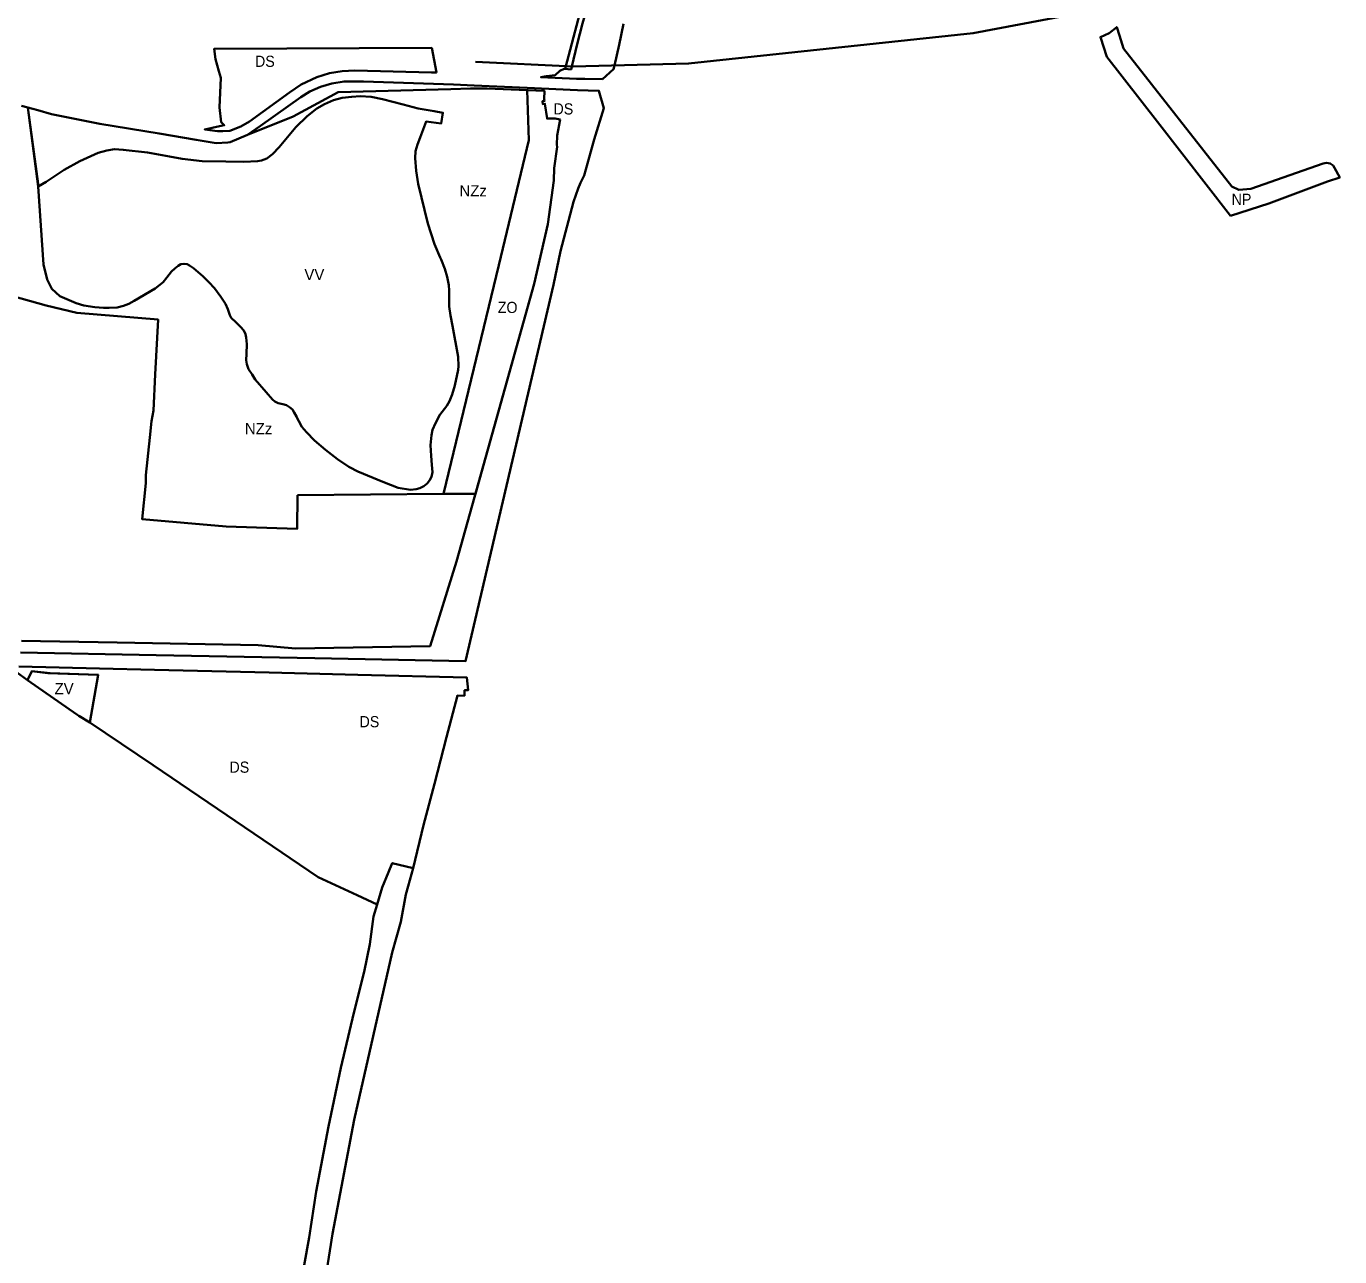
# Model space of a CAD drawing. Extents: x -650276 to -642489, y -1074311 to -1066720.
# Drawn here: x -645637 to -644229, y -1072023 to -1070703 of the extents above; entities that cross this region are included whole.
import ezdxf

# ---------------------------------------------------------------- set-up
doc = ezdxf.new("R2010")
doc.units = 0
doc.header["$LTSCALE"] = 4.8
for name, color, linetype, lineweight in [('15', 7, 'Continuous', 35), ('24', 7, 'Continuous', 35), ('40', 7, 'Continuous', 35), ('42', 7, 'Continuous', 35), ('45', 7, 'Continuous', 35), ('46', 7, 'Continuous', 35), ('48', 7, 'Continuous', 35), ('54', 7, 'Continuous', 35)]:
    doc.layers.add(name, color=color, linetype=linetype, lineweight=lineweight)
doc.layers.add('62', color=7, linetype='Continuous')

msp = doc.modelspace()

# ---------------------------------------------------------------- linework, layer by layer
at = {"layer": '15'}
msp.add_lwpolyline([(-645039.574, -1070675.065), (-645045.493, -1070696.321), (-645059.308, -1070747.712), (-645059.403, -1070749.195), (-645053.21, -1070749.75), (-645052.4, -1070746.427), (-645046.63, -1070722.77), (-645041, -1070700.44), (-645033.53, -1070674.55)], dxfattribs=at)
at = {"layer": '24'}
for points in [[(-645041, -1070700.44), (-645046.63, -1070722.77), (-645052.4, -1070746.427), (-645053.21, -1070749.75), (-645060.46, -1070749.1), (-645065.17, -1070751.39), (-645070.3, -1070755.92), (-645079.38, -1070756.91), (-645085.58, -1070758.04), (-645047.39, -1070759.71), (-645038.44, -1070759.83), (-645019.57, -1070760.07), (-645007.68, -1070749.5), (-645006.739, -1070745.384), (-645001.71, -1070723.39), (-644997.14, -1070700.88)], [(-645643.56, -1071374.75), (-645497.84, -1071377.53), (-645327.76, -1071380.76), (-645166.34, -1071384.07), (-645071.99, -1070980.72), (-645064.39, -1070944.7), (-645050.47, -1070891.48), (-645045.74, -1070877.19), (-645043, -1070871.35), (-645039.25, -1070863.33), (-645028.25, -1070824.83), (-645018.18, -1070791.34), (-645023.25, -1070772.62), (-645046.46, -1070771.98), (-645100.32, -1070769.5), (-645156.988, -1070766.884), (-645179.18, -1070765.86), (-645275.8, -1070762.66), (-645296.51, -1070762.52), (-645309.78, -1070764.88), (-645321.9, -1070768.47), (-645333.12, -1070773.33), (-645342.94, -1070779.31), (-645385.99, -1070810.35), (-645400.05, -1070819.84), (-645351, -1070800), (-645303, -1070774), (-645182, -1070771), (-645161, -1070770), (-645143, -1070770), (-645081.75, -1070772.79), (-645081.85, -1070781.59), (-645081.57, -1070783.53), (-645083.95, -1070783.89), (-645083.49, -1070786.92), (-645081.13, -1070786.56), (-645081.13, -1070786.56), (-645078.85, -1070802.46), (-645070.2, -1070802.33), (-645065.01, -1070803.22), (-645068.07, -1070820.37), (-645068.52, -1070830.52), (-645068.07, -1070832.72), (-645071.18, -1070855.63), (-645071.77, -1070868.73), (-645078.23, -1070915.65), (-645092.67, -1070979.52), (-645176.14, -1071277.26), (-645204.341, -1071368.19), (-645348.55, -1071370.559), (-645388.619, -1071366.991), (-645539.738, -1071364.092), (-645642.431, -1071362.259)], [(-645647.727, -1071396.036), (-645635.795, -1071404.403), (-645631.44, -1071394.9), (-645614.201, -1071396.844), (-645560.11, -1071398.7), (-645569.07, -1071449.88), (-645501.37, -1071495.68), (-645393.34, -1071568.75), (-645324.17, -1071615.53), (-645324.17, -1071615.53), (-645305.78, -1071624.13), (-645282.54, -1071634.997), (-645261.094, -1071645.025), (-645255.662, -1071626.67), (-645248.786, -1071610.383), (-645244.81, -1071600.61), (-645222.48, -1071606.08), (-645222.48, -1071606.08), (-645211.27, -1071560.01), (-645199.61, -1071515.68), (-645186.67, -1071465.55), (-645175.06, -1071420.93), (-645167.58, -1071421.19), (-645167.37, -1071415.2), (-645163.56, -1071415.3), (-645164.76, -1071401.79), (-645281.92, -1071398.82), (-645376.87, -1071396.41), (-645499.65, -1071393.3), (-645558.9, -1071391.8), (-645645.368, -1071389.96)], [(-645339.904, -1072462.677), (-645347.551, -1072443.527), (-645347.677, -1072391.355), (-645346.62, -1072330.914), (-645343.458, -1072278.998), (-645339.908, -1072235.158), (-645335.367, -1072185.207), (-645325.498, -1072102.789), (-645309.01, -1071998.147), (-645285.617, -1071875.733), (-645244.798, -1071696.585), (-645235.793, -1071663.703), (-645230.436, -1071634.261), (-645227.905, -1071625.277), (-645222.48, -1071606.08)], [(-645339.904, -1072462.677), (-645347.551, -1072443.527), (-645347.677, -1072391.355), (-645346.62, -1072330.914), (-645343.458, -1072278.998), (-645339.908, -1072235.158), (-645335.367, -1072185.207), (-645325.498, -1072102.789), (-645309.01, -1071998.147), (-645285.617, -1071875.733), (-645244.798, -1071696.585), (-645235.793, -1071663.703), (-645230.436, -1071634.261), (-645227.905, -1071625.277), (-645222.48, -1071606.08)], [(-645222.48, -1071606.08), (-645244.81, -1071600.61), (-645248.786, -1071610.383), (-645255.662, -1071626.67)], [(-645222.48, -1071606.08), (-645244.81, -1071600.61), (-645248.786, -1071610.383), (-645255.662, -1071626.67)], [(-645255.662, -1071626.67), (-645261.094, -1071645.025), (-645264.841, -1071657.687), (-645269.077, -1071687.396), (-645274.868, -1071717.176), (-645286.175, -1071761.228), (-645300.076, -1071820.179), (-645313.153, -1071883.081), (-645326.343, -1071952.807)], [(-645255.662, -1071626.67), (-645261.094, -1071645.025), (-645264.841, -1071657.687), (-645269.077, -1071687.396), (-645274.868, -1071717.176), (-645286.175, -1071761.228), (-645300.076, -1071820.179), (-645313.153, -1071883.081)], [(-645313.153, -1071883.081), (-645326.343, -1071952.807), (-645334.118, -1072001.954), (-645339.455, -1072031.565), (-645344.819, -1072081.225), (-645351.358, -1072130.815), (-645361.317, -1072232.824), (-645364.435, -1072280.268), (-645366.951, -1072331.609), (-645370.624, -1072401.447), (-645372.228, -1072438.764)], [(-645326.343, -1071952.807), (-645334.118, -1072001.954), (-645339.455, -1072031.565), (-645344.819, -1072081.225), (-645351.358, -1072130.815), (-645361.317, -1072232.824), (-645364.435, -1072280.268), (-645366.951, -1072331.609), (-645370.624, -1072401.447), (-645372.228, -1072438.764)]]:
    msp.add_lwpolyline(points, dxfattribs=at)
msp.add_lwpolyline([(-645202.41, -1070726.571), (-645197.539, -1070753.128), (-645202.96, -1070752.89), (-645285.11, -1070750.69), (-645298.41, -1070751.48), (-645312.2, -1070753.77), (-645325.82, -1070757.94), (-645342.41, -1070765.76), (-645354.98, -1070774.28), (-645398.04, -1070805.44), (-645407.37, -1070810.95), (-645419.18, -1070815.44), (-645426.36, -1070815.78), (-645432.07, -1070816.05), (-645445.81, -1070814.06), (-645429.993, -1070810.647), (-645424.969, -1070809.563), (-645428.39, -1070806.09), (-645430, -1070790.68), (-645428.73, -1070758.67), (-645430.84, -1070751.43), (-645434.53, -1070738.77), (-645435.711, -1070727.497)], close=True, dxfattribs=at)
at = {"layer": '40'}
msp.add_lwpolyline([(-645583.18, -1071441.3), (-645580.947, -1071442.658), (-645569.07, -1071449.88), (-645560.11, -1071398.7), (-645611.58, -1071397.14), (-645631.44, -1071394.9), (-645635.795, -1071404.403)], close=True, dxfattribs=at)
at = {"layer": '42'}
for points in [[(-645155.777, -1071204.626), (-645092.67, -1070979.52), (-645078.23, -1070915.65), (-645071.77, -1070868.73), (-645071.18, -1070855.63), (-645068.07, -1070832.72), (-645068.52, -1070830.52), (-645068.07, -1070820.37), (-645065.01, -1070803.22), (-645070.2, -1070802.33), (-645078.85, -1070802.46), (-645081.13, -1070786.56), (-645081.13, -1070786.56), (-645083.49, -1070786.92), (-645083.95, -1070783.89), (-645081.57, -1070783.53), (-645081.85, -1070781.59), (-645081.75, -1070772.79), (-645100.268, -1070771.946)], [(-645100.268, -1070771.946), (-645098.438, -1070825.558), (-645130.749, -1070959.561)], [(-645130.749, -1070959.561), (-645130.749, -1070959.561), (-645189.902, -1071204.885)], [(-645189.902, -1071204.885), (-645186.64, -1071204.86), (-645155.777, -1071204.626)]]:
    msp.add_lwpolyline(points, dxfattribs=at)
at = {"layer": '45'}
for points in [[(-645192.548, -1070953.47), (-645193.51, -1070951.2), (-645199.714, -1070937.126), (-645206.872, -1070914.991), (-645216.991, -1070872.38), (-645219.351, -1070858.481), (-645220.312, -1070845.02), (-645219.787, -1070837.502), (-645217.778, -1070830.159), (-645215.063, -1070822.589), (-645208.696, -1070805.535), (-645192.298, -1070807.665), (-645190.59, -1070796.152), (-645200.111, -1070794.621), (-645217.086, -1070791.58), (-645233.003, -1070787.399), (-645255.407, -1070781.443), (-645267.315, -1070779.162), (-645279.349, -1070778.402), (-645288.343, -1070778.909), (-645298.731, -1070780.176), (-645307.923, -1070782.557), (-645317.677, -1070786.866), (-645325.785, -1070791.428), (-645336.046, -1070799.793), (-645348.318, -1070811.675), (-645366.02, -1070832.94), (-645373.241, -1070840.417), (-645379.448, -1070845.106), (-645385.148, -1070847.387), (-645389.329, -1070848.148), (-645404.15, -1070848.781), (-645423.364, -1070848.402), (-645448.7, -1070847.895), (-645470.235, -1070845.487), (-645483.61, -1070843.208), (-645507.299, -1070838.899), (-645533.268, -1070835.731), (-645542.642, -1070835.35), (-645550.832, -1070836.602), (-645560.079, -1070839.137), (-645579.841, -1070848.008), (-645596.689, -1070857.387), (-645615.817, -1070870.187), (-645624.321, -1070875.224), (-645618.798, -1070958.861), (-645615, -1070975), (-645610, -1070985), (-645601.41, -1070992.83), (-645583.707, -1071000.16), (-645575.406, -1071002.782), (-645563.698, -1071004.618), (-645554.524, -1071005.405), (-645548.534, -1071005.316), (-645539.622, -1071004.966), (-645533.156, -1071003.131), (-645527.302, -1071001.033), (-645521.535, -1070997.886), (-645499.204, -1070984.54), (-645494.223, -1070980.781), (-645490.641, -1070977.722), (-645486.534, -1070972.652), (-645481.466, -1070966.271), (-645477.971, -1070963.036), (-645474.301, -1070960.414), (-645471.418, -1070958.578), (-645468.185, -1070957.966), (-645464.865, -1070958.491), (-645462.069, -1070959.89), (-645457.875, -1070962.949), (-645452.982, -1070967.057), (-645448.001, -1070971.341), (-645441.361, -1070977.635), (-645435.443, -1070984.082), (-645428.541, -1070993.348), (-645423.648, -1071000.865), (-645421.21, -1071006.61), (-645419.026, -1071013.254), (-645417.453, -1071016.051), (-645412.735, -1071020.771), (-645407.492, -1071025.841), (-645404.172, -1071029.687), (-645402.194, -1071033.492), (-645401.408, -1071037.251), (-645400.796, -1071044.157), (-645401.233, -1071054.647), (-645401.408, -1071061.465), (-645400.796, -1071065.748), (-645398.979, -1071070.938), (-645395.234, -1071076.602), (-645395.222, -1071076.62), (-645391.902, -1071082.302), (-645380.193, -1071095.851), (-645373.291, -1071103.543), (-645370.698, -1071105.6), (-645367.028, -1071107.348), (-645362.223, -1071108.484), (-645358.326, -1071109.586), (-645358.203, -1071109.621), (-645354.883, -1071111.631)], [(-645354.883, -1071111.631), (-645353.555, -1071112.92), (-645352, -1071114.429), (-645349.99, -1071117.401), (-645347.631, -1071121.771), (-645345.097, -1071126.754), (-645341.689, -1071132.873), (-645336.884, -1071138.467), (-645328.059, -1071147.471), (-645316.308, -1071157.576), (-645303.551, -1071167.541), (-645291.581, -1071175.845), (-645290.83, -1071176.217), (-645281.707, -1071180.74), (-645254.845, -1071191.919), (-645238.506, -1071198.212), (-645225.487, -1071200.398), (-645225.487, -1071200.398), (-645219.283, -1071199.786), (-645215.351, -1071198.562), (-645211.07, -1071196.464), (-645207.575, -1071193.492), (-645205.049, -1071190.531), (-645202.777, -1071186.423), (-645201.903, -1071181.615), (-645202.34, -1071173.66), (-645203.301, -1071164.132), (-645203.738, -1071152.537), (-645202.951, -1071141.698), (-645201.648, -1071136.226), (-645198.678, -1071128.971), (-645193.872, -1071120.142), (-645186.284, -1071110.216), (-645183.401, -1071105.408), (-645180.692, -1071098.24), (-645177.809, -1071088.625), (-645174.225, -1071071.8), (-645173.788, -1071067.691), (-645174.225, -1071057.989), (-645180.164, -1071024.56), (-645182.261, -1071013.633), (-645183.746, -1071003.786), (-645183.833, -1070986.74), (-645184.357, -1070981.146), (-645185.843, -1070972.23), (-645188.377, -1070963.313), (-645192.548, -1070953.47)]]:
    msp.add_lwpolyline(points, dxfattribs=at)
at = {"layer": '46'}
for points in [[(-645161, -1070770), (-645182, -1070771), (-645303, -1070774), (-645351, -1070800), (-645400.05, -1070819.84), (-645418.67, -1070827.72), (-645421.09, -1070827.89), (-645433.49, -1070828.76), (-645455.184, -1070825.042), (-645494.82, -1070818.45), (-645558.3, -1070808), (-645610.25, -1070797.55), (-645625, -1070793.5), (-645635.482, -1070790.628), (-645624.513, -1070872.314), (-645624.321, -1070875.224), (-645615.817, -1070870.187), (-645596.689, -1070857.387), (-645579.841, -1070848.008), (-645560.079, -1070839.137), (-645550.832, -1070836.602), (-645542.642, -1070835.35), (-645533.268, -1070835.731), (-645507.299, -1070838.899), (-645483.61, -1070843.208), (-645470.235, -1070845.487), (-645448.7, -1070847.895), (-645423.364, -1070848.402), (-645404.15, -1070848.781), (-645389.329, -1070848.148), (-645385.148, -1070847.387), (-645379.448, -1070845.106), (-645373.241, -1070840.417), (-645366.02, -1070832.94), (-645348.318, -1070811.675), (-645336.046, -1070799.793), (-645325.785, -1070791.428), (-645317.677, -1070786.866), (-645307.923, -1070782.557), (-645298.731, -1070780.176), (-645288.343, -1070778.909), (-645279.349, -1070778.402), (-645267.315, -1070779.162), (-645255.407, -1070781.443), (-645233.003, -1070787.399), (-645217.086, -1070791.58), (-645200.111, -1070794.621), (-645190.59, -1070796.152), (-645192.298, -1070807.665), (-645208.696, -1070805.535), (-645215.063, -1070822.589), (-645217.778, -1070830.159), (-645219.787, -1070837.502), (-645220.312, -1070845.02), (-645219.351, -1070858.481), (-645216.991, -1070872.38), (-645206.872, -1070914.991), (-645199.714, -1070937.126), (-645193.51, -1070951.2), (-645192.548, -1070953.47), (-645188.377, -1070963.313), (-645185.843, -1070972.23), (-645184.357, -1070981.146), (-645183.833, -1070986.74), (-645183.746, -1071003.786), (-645182.261, -1071013.633), (-645180.164, -1071024.56), (-645174.225, -1071057.989), (-645173.788, -1071067.691), (-645173.788, -1071067.691), (-645174.225, -1071071.8), (-645177.809, -1071088.625), (-645180.692, -1071098.24), (-645183.401, -1071105.408), (-645183.401, -1071105.408), (-645186.284, -1071110.216), (-645193.872, -1071120.142), (-645193.872, -1071120.142), (-645198.678, -1071128.971), (-645198.678, -1071128.971), (-645201.648, -1071136.226), (-645202.951, -1071141.698), (-645202.951, -1071141.698), (-645203.738, -1071152.537), (-645203.738, -1071152.537), (-645203.301, -1071164.132), (-645202.34, -1071173.66), (-645201.903, -1071181.615), (-645201.903, -1071181.615), (-645202.777, -1071186.423), (-645202.777, -1071186.423), (-645205.049, -1071190.531), (-645207.575, -1071193.492), (-645207.575, -1071193.492), (-645211.07, -1071196.464), (-645211.07, -1071196.464), (-645215.351, -1071198.562), (-645219.283, -1071199.786), (-645219.283, -1071199.786), (-645225.487, -1071200.398), (-645225.487, -1071200.398)], [(-645346.31, -1071206.07), (-645189.902, -1071204.885), (-645130.749, -1070959.561), (-645098.438, -1070825.558), (-645100.268, -1070771.946), (-645143, -1070770), (-645161, -1070770)], [(-645225.487, -1071200.398), (-645238.506, -1071198.212), (-645254.845, -1071191.919), (-645281.707, -1071180.74), (-645290.83, -1071176.217), (-645291.581, -1071175.845), (-645303.551, -1071167.541), (-645316.308, -1071157.576), (-645328.059, -1071147.471), (-645336.884, -1071138.467), (-645341.689, -1071132.873), (-645345.097, -1071126.754), (-645349.99, -1071117.401), (-645352, -1071114.429), (-645354.883, -1071111.631), (-645358.203, -1071109.621), (-645362.223, -1071108.484), (-645367.028, -1071107.348), (-645370.698, -1071105.6), (-645373.291, -1071103.543), (-645380.193, -1071095.851), (-645391.902, -1071082.302), (-645395.222, -1071076.62), (-645398.979, -1071070.938), (-645400.796, -1071065.748), (-645401.408, -1071061.465), (-645401.233, -1071054.647), (-645400.796, -1071044.157), (-645401.408, -1071037.251), (-645402.194, -1071033.492), (-645404.172, -1071029.687), (-645407.492, -1071025.841), (-645412.735, -1071020.771), (-645417.453, -1071016.051), (-645419.026, -1071013.254), (-645421.21, -1071006.61), (-645423.648, -1071000.865), (-645428.541, -1070993.348), (-645435.443, -1070984.082), (-645441.361, -1070977.635), (-645448.001, -1070971.341), (-645457.875, -1070962.949), (-645462.069, -1070959.89), (-645464.865, -1070958.491), (-645468.185, -1070957.966), (-645471.418, -1070958.578), (-645474.301, -1070960.414), (-645477.971, -1070963.036), (-645481.466, -1070966.271), (-645486.534, -1070972.652), (-645490.641, -1070977.722), (-645494.223, -1070980.781), (-645499.204, -1070984.54), (-645521.535, -1070997.886), (-645527.302, -1071001.033), (-645533.156, -1071003.131), (-645539.622, -1071004.966), (-645548.534, -1071005.316), (-645554.524, -1071005.405), (-645563.698, -1071004.618), (-645575.406, -1071002.782), (-645583.707, -1071000.16), (-645601.41, -1070992.83), (-645610, -1070985), (-645615, -1070975), (-645618.798, -1070958.861), (-645624.321, -1070875.224), (-645635.482, -1070790.628), (-645642.52, -1070788.7)], [(-645676.292, -1070985.89), (-645615.899, -1071002.753), (-645583.18, -1071010.7), (-645495.87, -1071017.81), (-645498.931, -1071076.631)], [(-645498.931, -1071076.631), (-645500.94, -1071115.24), (-645503.08, -1071126.98), (-645504.79, -1071144.18), (-645508.912, -1071184.7)], [(-645508.912, -1071184.7), (-645509.22, -1071193.44), (-645512.84, -1071231.9), (-645423.08, -1071239.85)], [(-645423.08, -1071239.85), (-645346.67, -1071242.07), (-645346.31, -1071206.07)]]:
    msp.add_lwpolyline(points, dxfattribs=at)
at = {"layer": '48'}
msp.add_lwpolyline([(-644346.21, -1070906.61), (-644305.07, -1070893.39), (-644242.29, -1070869.82), (-644229.12, -1070865.52), (-644234.66, -1070855.08), (-644236.3, -1070852.87), (-644239.47, -1070850.71), (-644243.15, -1070849.89), (-644246.93, -1070850.52), (-644282.77, -1070863.19), (-644324.34, -1070877.71), (-644337.15, -1070878.64), (-644344.86, -1070875.09), (-644460.82, -1070727.21), (-644465.31, -1070713.25), (-644468.1, -1070704.23), (-644476.35, -1070710.99), (-644485.61, -1070714.95), (-644478.67, -1070736.28), (-644424.37, -1070806.03)], close=True, dxfattribs=at)
at = {"layer": '54'}
msp.add_lwpolyline([(-645155.795, -1070741.501), (-645051.039, -1070746.492), (-644927.167, -1070743.394), (-644622.134, -1070710.86), (-644498.737, -1070687.652), (-644252.543, -1070613.291)], dxfattribs=at)

# ---------------------------------------------------------------- texts
at = {"layer": '62', "width": 0.95}
for s, p in [('DS', (-645392, -1070747)), ('DS', (-645072.003, -1070798.001)), ('NP', (-644345, -1070894.967)), ('ZO', (-645131.758, -1071010.853)), ('DS', (-645279.957, -1071454.984)), ('DS', (-645419.407, -1071503.717))]:
    msp.add_text(s, height=12, dxfattribs=at).set_placement(p)
at = {"layer": '62'}
for s, p in [('NZz', (-645172.866, -1070885.823)), ('VV', (-645339.075, -1070975.614)), ('NZz', (-645402.866, -1071140.823)), ('ZV', (-645606.931, -1071419.591))]:
    msp.add_text(s, height=12, dxfattribs=at).set_placement(p)

doc.saveas('drawing.dxf')
